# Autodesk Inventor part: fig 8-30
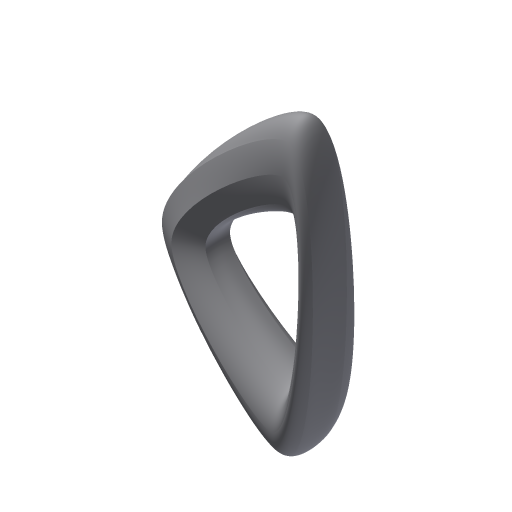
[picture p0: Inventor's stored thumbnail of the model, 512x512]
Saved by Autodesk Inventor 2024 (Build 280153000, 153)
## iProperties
Created: 2008-06
Part Number: fig 8-30
Document SubType Name: Modeling
Designer: CADCIM
Density: 1 g/cm^3
Material: Generic
Appearance: Default
Author: CADCIM
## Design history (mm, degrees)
sketch "Sketch1"
  geometry: L1 (-0.077, 5.773)-(4.961, 2.953); L2 (4.961, 2.953)-(5.038, -2.82); L3 (5.038, -2.82)-(0.077, -5.773); L4 (0.077, -5.773)-(-4.961, -2.953); L5 (-4.961, -2.953)-(-5.038, 2.82); L6 (-5.038, 2.82)-(-0.077, 5.773); 1 further point
  constraints: 12 end point, 13 other
  dimensions: "d0" = 10 distance between parallel lines of L2 L5
workplane "Work Plane1"
sketch "Sketch2"
  geometry: C1 r 7.5 at (-0.159, -25); 1 further point
  constraints: 1 centre point
  dimensions: "d2" = 15 diameter of C1; "d3" = 25 vertical distance of C1.centre point (0, 0)
sketch "Sketch3" dims "d4" = 10, "d5" = 5
  geometry: 2 further points; 1 other entity
  constraints: 2 other
  dimensions: "d6" = 25 vertical distance of point (0.175, 25) point (0, 0)
loft "Loft1" sketch "Sketch2", "Sketch3" dims "d7" = 0, "d8" = 90 deg, "d9" = 0, "d10" = 90 deg, "d11" = 0, "d12" = 90 deg
body "Solid1"
other parameters: "d1" = 25
